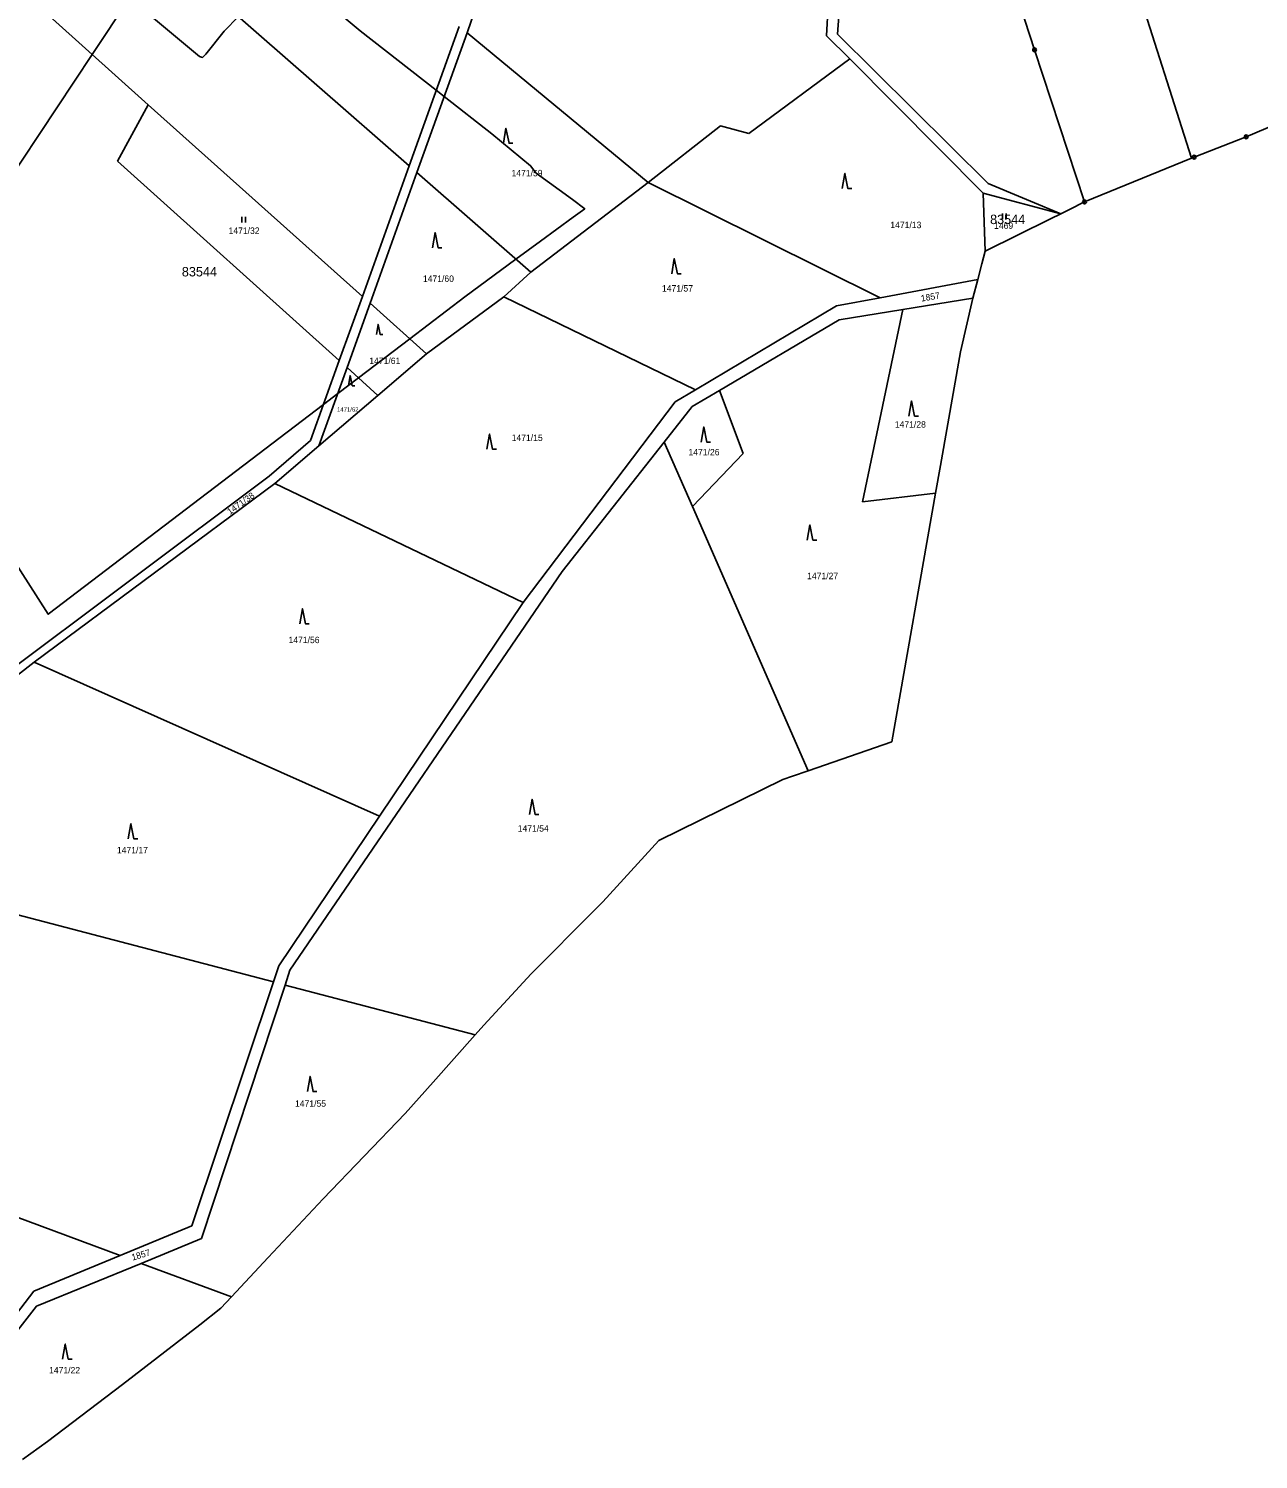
# Model space of a CAD drawing. Extents: x -445050 to -440454, y -1134563 to -1129741.
# Drawn here: x -442919.2 to -442593.5, y -1133322.6 to -1132943.7 of the extents above; entities that cross this region are included whole.
import ezdxf

# ---------------------------------------------------------------- set-up
doc = ezdxf.new("R2010")
doc.units = 0
for name, color, linetype in [('Vrstva 1', 7, 'Continuous'), ('Vrstva 13', 7, 'Continuous'), ('Vrstva 16', 7, 'Continuous'), ('Vrstva 18', 7, 'Continuous'), ('Vrstva 24', 7, 'Continuous'), ('Vrstva 25', 7, 'Continuous'), ('Vrstva 52', 7, 'Continuous'), ('Vrstva 53', 7, 'Continuous')]:
    doc.layers.add(name, color=color, linetype=linetype)

msp = doc.modelspace()

# ---------------------------------------------------------------- linework, layer by layer
at = {"layer": 'Vrstva 1'}
for points in [[(-442640.99, -1132884.33), (-442611.14, -1132977.99)], [(-442961.89, -1132897.04), (-442887.54, -1132963.84)], [(-442916.18, -1132894.47), (-442818.38, -1132980.02)], [(-442669.65, -1132897.51), (-442652.73, -1132949.29)], [(-442803.06, -1132944.79), (-442792.84, -1132915.11)], [(-442703.59, -1132927.17), (-442704.94, -1132945.11)], [(-442706.98, -1132929.23), (-442707.8, -1132945.54)], [(-442805.12, -1132943.09), (-442818.38, -1132980.02)], [(-442816.33, -1132981.81), (-442803.06, -1132944.79)], [(-442755.09, -1132984.47), (-442803.06, -1132944.79)], [(-442707.8, -1132945.54), (-442701.67, -1132951.7)], [(-442704.94, -1132945.11), (-442665.03, -1132984.7)], [(-442639.52, -1132989.58), (-442652.73, -1132949.29)], [(-442728.45, -1132971.42), (-442701.67, -1132951.7)], [(-442701.67, -1132951.7), (-442666.32, -1132987.26)], [(-442887.54, -1132963.84), (-442895.64, -1132978.78)], [(-442887.54, -1132963.84), (-442830.78, -1133014.58)], [(-442755.09, -1132984.47), (-442735.93, -1132969.41)], [(-442735.93, -1132969.41), (-442728.45, -1132971.42)], [(-442895.64, -1132978.78), (-442836.89, -1133031.61)], [(-442818.38, -1132980.02), (-442830.78, -1133014.58)], [(-442828.73, -1133016.41), (-442816.33, -1132981.81)], [(-442816.33, -1132981.81), (-442786.18, -1133008.19)], [(-442786.18, -1133008.19), (-442755.09, -1132984.47)], [(-442755.09, -1132984.47), (-442693.6, -1133014.93)], [(-442665.03, -1132984.7), (-442645.79, -1132992.69)], [(-442666.32, -1132987.26), (-442665.82, -1133002.63)], [(-442645.79, -1132992.69), (-442666.32, -1132987.26)], [(-442793.32, -1133014.67), (-442786.18, -1133008.19)], [(-442693.6, -1133014.93), (-442667.79, -1133010.13)], [(-442830.78, -1133014.58), (-442836.89, -1133031.61)], [(-442813.75, -1133029.81), (-442793.32, -1133014.67)], [(-442793.32, -1133014.67), (-442742.58, -1133039.37)], [(-442693.6, -1133014.93), (-442705.17, -1133017.05)], [(-442687.62, -1133018.05), (-442669.09, -1133015.08)], [(-442834.84, -1133033.45), (-442828.73, -1133016.41)], [(-442828.73, -1133016.41), (-442813.75, -1133029.81)], [(-442705.17, -1133017.05), (-442742.58, -1133039.37)], [(-442704.52, -1133020.76), (-442687.62, -1133018.05)], [(-442687.62, -1133018.05), (-442698.31, -1133069.01)], [(-442736.16, -1133039.49), (-442704.52, -1133020.76)], [(-442826.64, -1133040.83), (-442813.75, -1133029.81)], [(-442836.89, -1133031.61), (-442844.5, -1133052.8)], [(-442842.28, -1133054.2), (-442834.84, -1133033.45)], [(-442834.84, -1133033.45), (-442826.64, -1133040.83)], [(-442842.28, -1133054.2), (-442826.64, -1133040.83)], [(-442742.58, -1133039.37), (-442747.9, -1133042.54)], [(-442736.16, -1133039.49), (-442743.41, -1133043.79)], [(-442729.89, -1133056.2), (-442736.16, -1133039.49)], [(-442747.9, -1133042.54), (-442788.22, -1133095.64)], [(-442743.41, -1133043.79), (-442750.82, -1133053.16)], [(-442844.5, -1133052.8), (-442855.44, -1133062.17)], [(-442777.88, -1133087.42), (-442750.82, -1133053.16)], [(-442750.82, -1133053.16), (-442743.31, -1133070.28)], [(-442853.95, -1133064.18), (-442842.28, -1133054.2)], [(-442743.31, -1133070.28), (-442729.89, -1133056.2)], [(-442855.44, -1133062.17), (-442928.16, -1133116.59)], [(-442917.69, -1133111.46), (-442853.95, -1133064.18)], [(-442853.95, -1133064.18), (-442788.22, -1133095.64)], [(-442698.31, -1133069.01), (-442678.94, -1133066.74)], [(-442743.31, -1133070.28), (-442712.69, -1133140.21)], [(-442849.97, -1133193.01), (-442777.88, -1133087.42)], [(-442788.22, -1133095.64), (-442826.27, -1133152.21)], [(-442983.1, -1133162.38), (-442917.69, -1133111.46)], [(-442917.69, -1133111.46), (-442826.27, -1133152.21)], [(-442826.27, -1133152.21), (-442852.94, -1133191.85)], [(-442854.32, -1133196.17), (-442983.1, -1133162.38)], [(-442852.94, -1133191.85), (-442854.32, -1133196.17)], [(-442849.97, -1133193.01), (-442851.27, -1133196.97)], [(-442854.32, -1133196.17), (-442875.92, -1133260.79)], [(-442851.27, -1133196.97), (-442873.39, -1133264.15)], [(-442851.27, -1133196.97), (-442800.86, -1133210.2)], [(-443049.39, -1133211.2), (-442894.94, -1133268.62)], [(-442875.92, -1133260.79), (-442894.94, -1133268.62)], [(-442889.37, -1133270.69), (-442873.39, -1133264.15)], [(-442894.94, -1133268.62), (-442917.79, -1133278.04)], [(-442917.09, -1133282.05), (-442889.37, -1133270.69)], [(-442865.44, -1133279.59), (-442889.37, -1133270.69)], [(-442917.79, -1133278.04), (-442943.64, -1133311.8)], [(-442934.98, -1133305), (-442917.09, -1133282.05)]]:
    msp.add_lwpolyline(points, dxfattribs=at)
at = {"layer": 'Vrstva 13'}
for points in [[(-442583.36, -1132966.7), (-442596.71, -1132972.33)], [(-442610.45, -1132977.71), (-442596.71, -1132972.33)], [(-442611.14, -1132977.99), (-442639.52, -1132989.58)], [(-442610.45, -1132977.71), (-442611.14, -1132977.99)], [(-442648.47, -1132994.02), (-442645.79, -1132992.69)], [(-442645.79, -1132992.69), (-442643.47, -1132991.54)], [(-442643.47, -1132991.54), (-442639.52, -1132989.58)], [(-442648.47, -1132994.02), (-442665.82, -1133002.63)], [(-442666.7, -1133005.99), (-442665.82, -1133002.63)], [(-442667.79, -1133010.13), (-442666.7, -1133005.99)], [(-442669.09, -1133015.08), (-442667.79, -1133010.13)], [(-442669.09, -1133015.08), (-442672.35, -1133029.29)], [(-442672.35, -1133029.29), (-442677.64, -1133059.37)], [(-442677.64, -1133059.37), (-442678.94, -1133066.74)], [(-442690.54, -1133132.6), (-442678.94, -1133066.74)], [(-442690.54, -1133132.6), (-442712.69, -1133140.21)], [(-442716.83, -1133141.63), (-442712.69, -1133140.21)], [(-442752.27, -1133158.73), (-442719.43, -1133142.52)], [(-442719.43, -1133142.52), (-442716.83, -1133141.63)], [(-442752.27, -1133158.73), (-442767.13, -1133174.95)], [(-442769.24, -1133177.06), (-442786.08, -1133193.98)], [(-442767.13, -1133174.95), (-442769.24, -1133177.06)], [(-442798.59, -1133207.65), (-442786.08, -1133193.98)], [(-442800.86, -1133210.2), (-442798.59, -1133207.65)], [(-442812.05, -1133222.74), (-442800.86, -1133210.2)], [(-442819.45, -1133231.01), (-442812.05, -1133222.74)], [(-442841.2, -1133253.59), (-442819.45, -1133231.01)], [(-442855.75, -1133269.14), (-442841.2, -1133253.59)], [(-442855.75, -1133269.14), (-442865.44, -1133279.59)], [(-442865.44, -1133279.59), (-442868.23, -1133282.6)], [(-442873.79, -1133286.94), (-442868.23, -1133282.6)], [(-442894.32, -1133302.75), (-442873.79, -1133286.94)], [(-442894.32, -1133302.75), (-442914.17, -1133317.9)], [(-442920.78, -1133322.61), (-442914.17, -1133317.9)]]:
    msp.add_lwpolyline(points, dxfattribs=at)
at = {"layer": 'Vrstva 24'}
for centre, radius in [((-442652.73, -1132949.29), 0.5), ((-442652.73, -1132949.29), 0.1), ((-442596.71, -1132972.33), 0.5), ((-442596.71, -1132972.33), 0.1), ((-442610.45, -1132977.71), 0.5), ((-442610.45, -1132977.71), 0.1), ((-442639.52, -1132989.58), 0.5), ((-442639.52, -1132989.58), 0.1)]:
    msp.add_circle(centre, radius, dxfattribs=at)
at = {"layer": 'Vrstva 25'}
for p, q in [((-442661.27, -1132994.1), (-442661.27, -1132992.6)), ((-442660.27, -1132994.1), (-442660.27, -1132992.6)), ((-442862.74, -1132994.98), (-442862.74, -1132993.48)), ((-442861.74, -1132994.98), (-442861.74, -1132993.48))]:
    msp.add_line(p, q, dxfattribs=at)
for points in [[(-442793.44, -1132974.05), (-442792.74, -1132970.05), (-442791.94, -1132974.05), (-442790.94, -1132974.05)], [(-442703.66, -1132986.04), (-442702.96, -1132982.04), (-442702.16, -1132986.04), (-442701.16, -1132986.04)], [(-442812.21, -1133001.69), (-442811.51, -1132997.69), (-442810.71, -1133001.69), (-442809.71, -1133001.69)], [(-442748.85, -1133008.59), (-442748.15, -1133004.59), (-442747.35, -1133008.59), (-442746.35, -1133008.59)], [(-442827.07, -1133024.7), (-442826.6, -1133022.02), (-442826.06, -1133024.7), (-442825.39, -1133024.7)], [(-442834.49, -1133038.24), (-442834.02, -1133035.56), (-442833.48, -1133038.24), (-442832.81, -1133038.24)], [(-442686, -1133046.28), (-442685.3, -1133042.28), (-442684.5, -1133046.28), (-442683.5, -1133046.28)], [(-442741.07, -1133053.17), (-442740.37, -1133049.17), (-442739.57, -1133053.17), (-442738.57, -1133053.17)], [(-442797.79, -1133055.06), (-442797.09, -1133051.06), (-442796.29, -1133055.06), (-442795.29, -1133055.06)], [(-442712.93, -1133079.13), (-442712.23, -1133075.13), (-442711.43, -1133079.13), (-442710.43, -1133079.13)], [(-442847.35, -1133101.31), (-442846.65, -1133097.31), (-442845.85, -1133101.31), (-442844.85, -1133101.31)], [(-442786.54, -1133151.78), (-442785.84, -1133147.78), (-442785.04, -1133151.78), (-442784.04, -1133151.78)], [(-442892.78, -1133158.27), (-442892.08, -1133154.27), (-442891.28, -1133158.27), (-442890.28, -1133158.27)], [(-442845.34, -1133225.19), (-442844.64, -1133221.19), (-442843.84, -1133225.19), (-442842.84, -1133225.19)], [(-442910.18, -1133296.06), (-442909.48, -1133292.06), (-442908.68, -1133296.06), (-442907.68, -1133296.06)]]:
    msp.add_lwpolyline(points, dxfattribs=at)
at = {"layer": 'Vrstva 52'}
for points in [[(-442941.41, -1133056.01), (-442956.09, -1133031.53), (-442935.17, -1133000), (-442902.35, -1132950.54), (-442892.51, -1132935.72), (-442889.26, -1132938.29), (-442873.93, -1132951.06), (-442873.08, -1132951.28), (-442872.23, -1132950.43), (-442867.36, -1132944.37), (-442863.61, -1132940.46), (-442863.33, -1132940.17), (-442852.86, -1132928.5), (-442848.39, -1132929.99), (-442831.36, -1132944.25)], [(-442831.36, -1132944.25), (-442811.19, -1132959.99), (-442809.1, -1132961.63), (-442796.45, -1132971.5), (-442786.23, -1132980.01), (-442784.74, -1132981.93), (-442775.16, -1132988.95), (-442771.86, -1132991.37), (-442774.95, -1132993.64), (-442783.63, -1133000), (-442790.11, -1133004.75), (-442803.68, -1133014.71), (-442818.23, -1133025.8), (-442831.83, -1133036.16), (-442837.31, -1133040.33), (-442841.05, -1133043.18), (-442913.98, -1133098.76), (-442941.41, -1133056.01)], [(-443179.15, -1132962.93), (-443173.49, -1132993.25), (-443171.6, -1132999), (-443172.37, -1132999.26), (-443172.25, -1132999.92), (-443178.65, -1133006.98), (-443162.26, -1133037.43), (-443148.19, -1133059.98), (-443114.76, -1133075.24), (-443097.28, -1133090.91), (-443118.98, -1133115.33), (-443050.8, -1133209.14), (-443049.39, -1133211.2), (-442894.94, -1133268.62), (-442917.79, -1133278.04), (-442943.64, -1133311.8), (-443085.5, -1133235.99), (-443115.7, -1133259.74), (-443088.41, -1133297.31)], [(-442665.82, -1133002.63), (-442666.32, -1132987.26), (-442645.79, -1132992.69)], [(-442645.79, -1132992.69), (-442648.47, -1132994.02)], [(-442648.47, -1132994.02), (-442665.82, -1133002.63)]]:
    msp.add_lwpolyline(points, dxfattribs=at)

# ---------------------------------------------------------------- texts
at = {"layer": 'Vrstva 16'}
msp.add_text('1857', height=1.7, rotation=9.7987, dxfattribs=at).set_placement((-442682.69, -1133015.98))
at = {"layer": 'Vrstva 18'}
for s, height, p in [('1471/59', 1.7, (-442791.27, -1132982.78)), ('1471/32', 1.7, (-442866.22, -1132998.04)), ('1471/13', 1.7, (-442690.94, -1132996.52)), ('1469', 1.7, (-442663.45, -1132996.7)), ('1471/60', 1.7, (-442814.74, -1133010.75)), ('1471/57', 1.7, (-442751.42, -1133013.31)), ('1471/61', 1.7, (-442828.95, -1133032.5)), ('1471/62', 1.14, (-442837.49, -1133045.12)), ('1471/28', 1.7, (-442689.74, -1133049.34)), ('1471/15', 1.7, (-442791.23, -1133052.87)), ('1471/26', 1.7, (-442744.4, -1133056.69)), ('1471/27', 1.7, (-442712.98, -1133089.49)), ('1471/56', 1.7, (-442850.34, -1133106.43)), ('1471/54', 1.7, (-442789.63, -1133156.34)), ('1471/17', 1.7, (-442895.79, -1133162.09)), ('1471/55', 1.7, (-442848.62, -1133229.21)), ('1471/22', 1.7, (-442913.76, -1133299.83))]:
    msp.add_text(s, height=height, dxfattribs=at).set_placement(p)
for s, rotation, p in [('1471/38', 35.6022, (-442865.84, -1133072.5)), ('1857', 16.5105, (-442891.63, -1133269.98))]:
    msp.add_text(s, height=1.7, rotation=rotation, dxfattribs=at).set_placement(p)
at = {"layer": 'Vrstva 53'}
for p in [(-442664.51, -1132995.44), (-442878.59, -1133009.3)]:
    msp.add_text('83544', height=2.5, dxfattribs=at).set_placement(p)

doc.saveas('drawing.dxf')
